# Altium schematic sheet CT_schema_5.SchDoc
size 208 x 169 mm
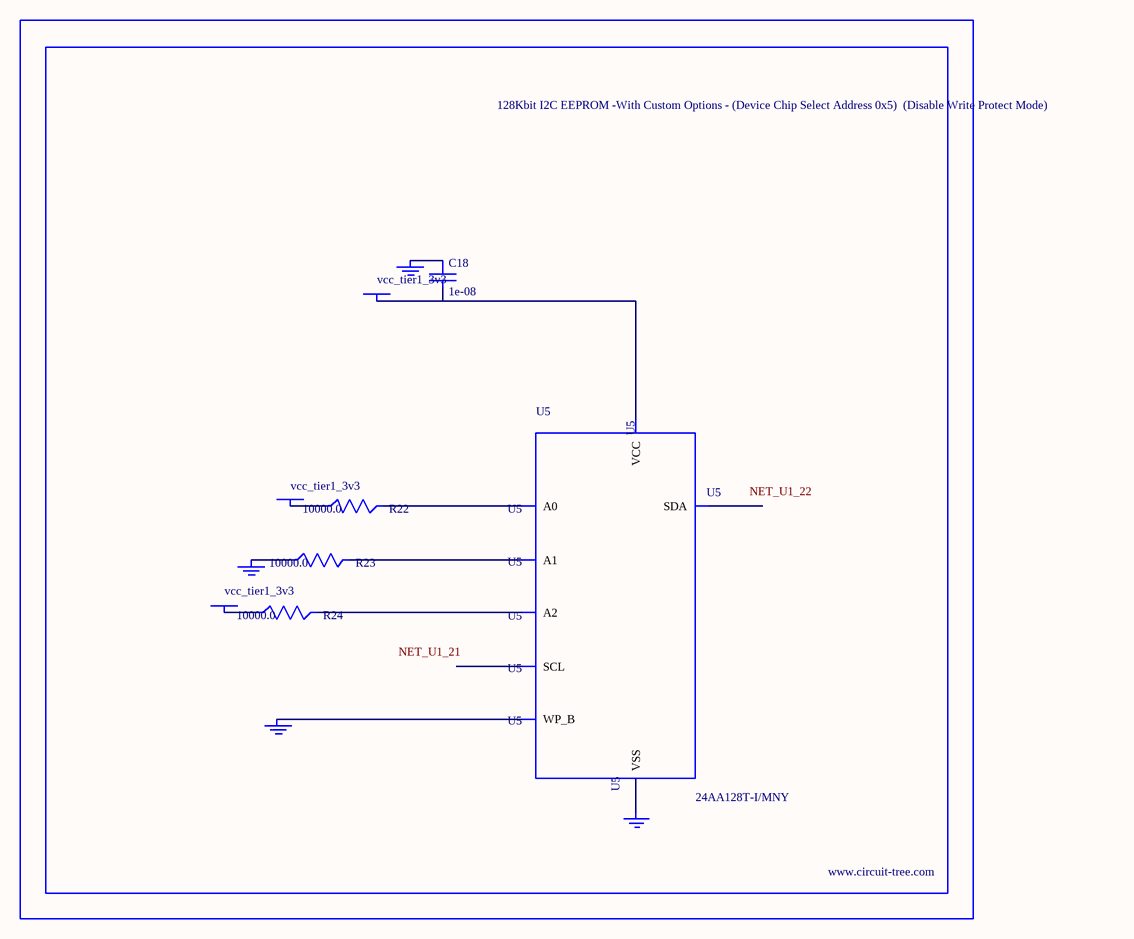
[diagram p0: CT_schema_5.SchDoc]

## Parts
BORDER4  (no value)
C18  1e-08  [C0402]
GND_INSTANCE_4_0  (no value)
GND_INSTANCE_4_1  (no value)
GND_INSTANCE_4_2  (no value)
GND_INSTANCE_4_3  (no value)
POWER_INSTANCE_4_0  vcc_tier1_3v3
POWER_INSTANCE_4_1  vcc_tier1_3v3
POWER_INSTANCE_4_2  vcc_tier1_3v3
R22  10000.0  [R0603]
R23  10000.0  [R0603]
R24  10000.0  [R0603]
U5  24AA128T-I/MNY  [TDFN-8/6MM]

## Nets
NetC18_1: C18.1 GND_INSTANCE_4_2.0(GND)
NetC18_2: C18.2 POWER_INSTANCE_4_2.0(PWR) U5.8(VCC)
NetGND_INSTANCE_4_0_0: GND_INSTANCE_4_0.0(GND) R23.1
NetGND_INSTANCE_4_1_0: GND_INSTANCE_4_1.0(GND) U5.7(WP_B)
NetGND_INSTANCE_4_3_0: GND_INSTANCE_4_3.0(GND) U5.4(VSS)
NetPOWER_INSTANCE_4_0_0: POWER_INSTANCE_4_0.0(PWR) R22.1
NetPOWER_INSTANCE_4_1_0: POWER_INSTANCE_4_1.0(PWR) R24.1
NetR22_2: R22.2 U5.1(A0)
NetR23_2: R23.2 U5.2(A1)
NetR24_2: R24.2 U5.3(A2)

Not connected (* = marked no-connect by the designer): U5 5(SDA) 6(SCL)

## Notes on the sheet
- Labels drawn without touching a wire or pin: NET_U1_21, NET_U1_22

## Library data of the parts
BORDER4 = BORDER_PAGE4
C18 = C0402C103K3RAC
GND_INSTANCE_4_0-GND_INSTANCE_4_3 = GND
POWER_INSTANCE_4_0-POWER_INSTANCE_4_2 = PWR
R22-R24 = RC0603JR-0710KL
